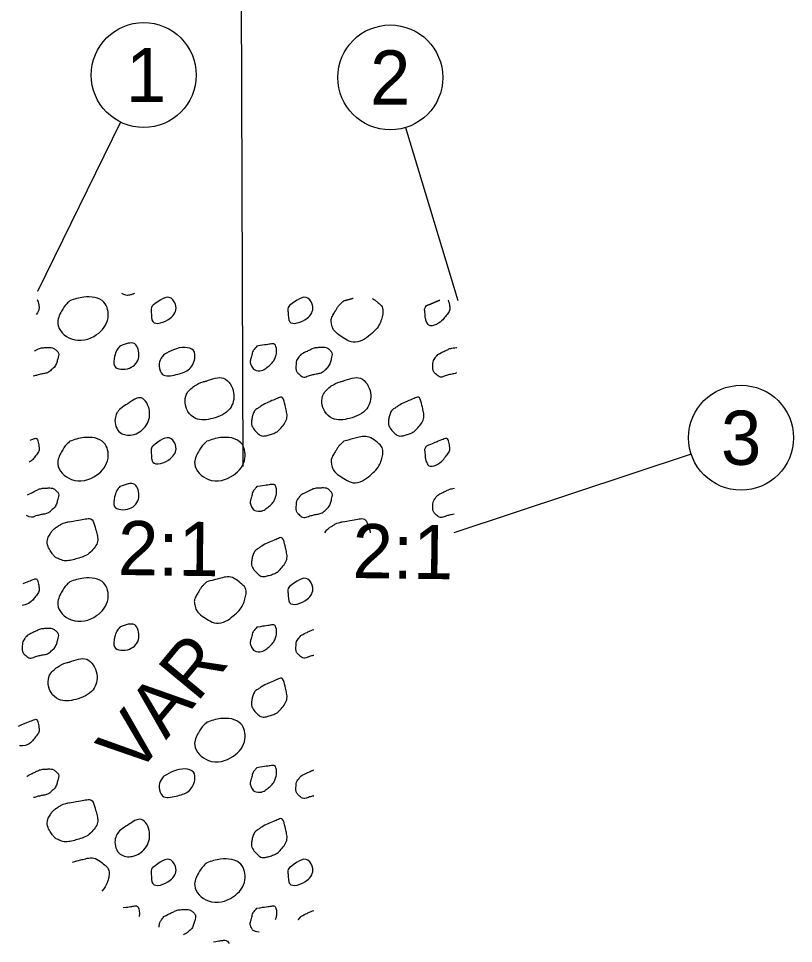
# Model space of a CAD drawing. Extents: x -1270 to 3371, y -118 to 220.
# Drawn here: x 98.85 to 118.87, y 155.01 to 178.92 of the extents above; entities that cross this region are included whole.
import ezdxf

# ---------------------------------------------------------------- set-up
doc = ezdxf.new("R2010")
doc.units = 0
for name, color, linetype in [('GE_P_Alignment', 7, 'Continuous'), ('GE_P_Alignment_100_Bearings', 7, 'Continuous'), ('TX_P_1', 7, 'Continuous')]:
    doc.layers.add(name, color=color, linetype=linetype)

msp = doc.modelspace()

# ---------------------------------------------------------------- linework, layer by layer
at = {"layer": 'GE_P_Alignment'}
for p, q in [((104.602, 180.507), (104.65, 167.338)), ((101.489, 176.239), (99.34, 171.86)), ((108.848, 176.097), (110.202, 171.63)), ((116.229, 167.658), (110.094, 165.63))]:
    msp.add_line(p, q, dxfattribs=at)
at = {"layer": 'GE_P_Alignment_100_Bearings'}
for points, degree in [([(99.33, 171.651), (99.36, 171.6), (99.377, 171.517), (99.382, 171.471), (99.388, 171.405), (99.357, 171.337), (99.311, 171.27)], 3), ([(101.848, 171.807), (101.829, 171.799), (101.809, 171.793), (101.789, 171.787), (101.706, 171.762), (101.604, 171.755), (101.517, 171.814)], 3), ([(107.99, 171.677), (108.036, 171.653), (108.082, 171.623), (108.128, 171.584), (108.263, 171.472), (108.272, 171.306), (108.236, 171.182), (108.191, 171.025), (108.092, 170.877), (107.94, 170.747), (107.75, 170.585), (107.486, 170.521), (107.292, 170.636), (107.134, 170.729), (106.968, 170.869), (106.938, 171.034), (106.919, 171.137), (106.972, 171.257), (107.033, 171.353), (107.076, 171.421), (107.114, 171.49), (107.171, 171.545), (107.198, 171.571), (107.225, 171.597), (107.252, 171.623)], 3), ([(107.252, 171.623), (107.333, 171.644), (107.415, 171.666), (107.496, 171.687)], 2), ([(109.946, 171.635), (109.971, 171.584), (109.985, 171.512), (109.989, 171.471), (109.999, 171.371), (109.922, 171.267), (109.84, 171.169), (109.729, 171.034), (109.448, 170.937), (109.39, 171.084), (109.359, 171.163), (109.354, 171.243), (109.351, 171.324), (109.349, 171.365), (109.334, 171.409), (109.355, 171.445), (109.366, 171.464), (109.377, 171.48), (109.388, 171.497)], 3), ([(109.388, 171.497), (109.504, 171.544), (109.62, 171.593), (109.736, 171.64)], 2), ([(99.265, 170.329), (99.284, 170.339), (99.303, 170.348), (99.323, 170.358), (99.414, 170.404), (99.524, 170.413), (99.623, 170.416), (99.697, 170.418), (99.768, 170.4), (99.834, 170.335), (99.895, 170.275), (99.886, 170.195), (99.868, 170.131), (99.839, 170.026), (99.8, 169.92), (99.698, 169.835), (99.598, 169.752), (99.492, 169.74), (99.384, 169.715), (99.336, 169.703), (99.284, 169.685), (99.233, 169.675)], 3), ([(105.007, 170.45), (105.134, 170.468), (105.261, 170.488), (105.388, 170.506), (105.502, 170.521), (105.528, 170.276), (105.493, 170.177), (105.453, 170.069), (105.354, 169.961), (105.253, 169.883), (105.148, 169.803), (104.927, 169.816), (104.866, 169.94), (104.828, 170.017), (104.847, 170.108), (104.868, 170.186), (104.884, 170.241), (104.891, 170.304), (104.927, 170.349), (104.953, 170.383), (104.98, 170.416), (105.007, 170.45)], 3), ([(106.144, 170.233), (106.227, 170.275), (106.311, 170.316), (106.394, 170.358), (106.486, 170.404), (106.595, 170.413), (106.695, 170.416), (106.769, 170.418), (106.84, 170.4), (106.906, 170.335), (106.967, 170.275), (106.958, 170.195), (106.94, 170.131), (106.911, 170.026), (106.871, 169.92), (106.769, 169.835), (106.669, 169.752), (106.563, 169.74), (106.456, 169.715), (106.343, 169.689), (106.214, 169.622), (106.104, 169.721), (106.032, 169.786), (106.016, 169.862), (106.018, 169.936), (106.02, 170.003), (106.028, 170.081), (106.07, 170.136), (106.095, 170.169), (106.119, 170.201), (106.144, 170.233)], 3), ([(110.165, 169.757), (110.108, 169.738), (110.05, 169.728), (109.992, 169.715), (109.879, 169.689), (109.75, 169.622), (109.64, 169.721), (109.567, 169.786), (109.552, 169.862), (109.554, 169.936), (109.556, 170.003), (109.564, 170.081), (109.606, 170.136), (109.631, 170.169), (109.655, 170.201), (109.68, 170.233)], 3), ([(109.68, 170.233), (109.763, 170.275), (109.847, 170.316), (109.93, 170.358), (110.005, 170.396), (110.093, 170.408), (110.177, 170.413)], 3), ([(105.211, 168.961), (105.328, 169.012), (105.445, 169.062), (105.563, 169.112), (105.684, 169.164), (105.743, 168.898), (105.77, 168.774), (105.798, 168.643), (105.764, 168.496), (105.658, 168.369), (105.559, 168.249), (105.445, 168.193), (105.325, 168.156), (105.229, 168.127), (105.108, 168.123), (105.014, 168.216), (104.9, 168.328), (104.858, 168.46), (104.881, 168.575), (104.899, 168.666), (104.942, 168.786), (105.027, 168.842), (105.088, 168.883), (105.15, 168.921), (105.211, 168.961)], 3), ([(108.747, 168.961), (108.864, 169.012), (108.981, 169.062), (109.098, 169.112), (109.22, 169.164), (109.279, 168.898), (109.306, 168.774), (109.334, 168.643), (109.3, 168.496), (109.194, 168.369), (109.095, 168.249), (108.981, 168.193), (108.861, 168.156), (108.765, 168.127), (108.644, 168.123), (108.55, 168.216), (108.436, 168.328), (108.394, 168.46), (108.417, 168.575), (108.435, 168.666), (108.477, 168.786), (108.563, 168.842), (108.624, 168.883), (108.685, 168.921), (108.747, 168.961)], 3), ([(99.151, 168.018), (99.186, 168.032), (99.221, 168.046), (99.256, 168.059), (99.334, 168.089), (99.375, 167.915), (99.382, 167.841), (99.391, 167.741), (99.315, 167.637), (99.233, 167.538), (99.205, 167.505), (99.166, 167.473), (99.123, 167.448)], 3), ([(107.252, 167.992), (107.37, 168.024), (107.489, 168.055), (107.608, 168.086), (107.781, 168.13), (107.955, 168.099), (108.128, 167.954), (108.263, 167.842), (108.272, 167.675), (108.236, 167.551), (108.191, 167.395), (108.092, 167.246), (107.94, 167.116), (107.75, 166.954), (107.486, 166.89), (107.292, 167.006), (107.134, 167.099), (106.968, 167.239), (106.938, 167.404), (106.919, 167.507), (106.972, 167.626), (107.033, 167.722), (107.076, 167.791), (107.114, 167.86), (107.171, 167.915), (107.198, 167.941), (107.225, 167.967), (107.252, 167.992)], 3), ([(109.388, 167.866), (109.547, 167.93), (109.705, 167.999), (109.863, 168.059), (109.941, 168.089), (109.982, 167.915), (109.989, 167.841), (109.999, 167.741), (109.922, 167.637), (109.84, 167.538), (109.729, 167.404), (109.448, 167.306), (109.39, 167.454), (109.359, 167.532), (109.354, 167.613), (109.351, 167.694), (109.349, 167.734), (109.334, 167.779), (109.355, 167.815), (109.366, 167.833), (109.377, 167.849), (109.388, 167.866)], 3), ([(105.007, 166.819), (105.134, 166.838), (105.261, 166.858), (105.388, 166.875), (105.502, 166.89), (105.528, 166.645), (105.493, 166.547), (105.453, 166.438), (105.354, 166.331), (105.253, 166.253), (105.148, 166.172), (104.927, 166.186), (104.866, 166.309), (104.828, 166.387), (104.847, 166.477), (104.868, 166.555), (104.884, 166.61), (104.891, 166.673), (104.927, 166.718), (104.953, 166.752), (104.98, 166.786), (105.007, 166.819)], 3), ([(99.082, 166.607), (99.162, 166.648), (99.242, 166.688), (99.323, 166.728), (99.414, 166.773), (99.524, 166.782), (99.623, 166.785), (99.697, 166.787), (99.768, 166.77), (99.834, 166.704), (99.895, 166.644), (99.886, 166.564), (99.868, 166.501), (99.839, 166.396), (99.8, 166.289), (99.698, 166.204), (99.598, 166.121), (99.492, 166.109), (99.384, 166.084), (99.279, 166.06), (99.161, 166), (99.056, 166.072)], 3), ([(106.144, 166.603), (106.227, 166.644), (106.311, 166.686), (106.394, 166.728), (106.486, 166.773), (106.595, 166.782), (106.695, 166.785), (106.769, 166.787), (106.84, 166.77), (106.906, 166.704), (106.967, 166.644), (106.958, 166.564), (106.94, 166.501), (106.911, 166.396), (106.871, 166.289), (106.769, 166.204), (106.669, 166.121), (106.563, 166.109), (106.456, 166.084), (106.343, 166.058), (106.214, 165.991), (106.104, 166.09), (106.032, 166.155), (106.016, 166.231), (106.018, 166.306), (106.02, 166.372), (106.028, 166.451), (106.07, 166.506), (106.095, 166.539), (106.119, 166.57), (106.144, 166.603)], 3), ([(110.101, 166.109), (110.065, 166.1), (110.028, 166.093), (109.992, 166.084), (109.879, 166.058), (109.75, 165.991), (109.64, 166.09), (109.567, 166.155), (109.552, 166.231), (109.554, 166.306), (109.556, 166.372), (109.564, 166.451), (109.606, 166.506), (109.631, 166.539), (109.655, 166.57), (109.68, 166.603)], 3), ([(109.68, 166.603), (109.763, 166.644), (109.847, 166.686), (109.93, 166.728), (109.986, 166.755), (110.049, 166.77), (110.112, 166.777)], 3), ([(100.159, 165.913), (100.311, 165.939), (100.462, 165.968), (100.613, 165.989), (100.765, 166.01), (100.835, 165.751), (100.873, 165.609), (100.907, 165.48), (100.885, 165.323), (100.776, 165.203), (100.643, 165.055), (100.495, 164.998), (100.33, 164.95), (100.189, 164.909), (100.031, 164.893), (99.89, 164.953), (99.805, 164.989), (99.743, 165.051), (99.691, 165.131), (99.604, 165.265), (99.579, 165.449), (99.654, 165.576), (99.704, 165.66), (99.772, 165.734), (99.859, 165.789), (99.933, 165.836), (100.003, 165.88), (100.085, 165.898), (100.113, 165.903), (100.14, 165.909), (100.168, 165.915)], 3), ([(106.762, 165.63), (106.807, 165.691), (106.863, 165.746), (106.931, 165.789), (107.005, 165.836), (107.075, 165.88), (107.157, 165.898), (107.184, 165.903), (107.212, 165.909), (107.239, 165.915)], 3), ([(107.231, 165.913), (107.382, 165.939), (107.534, 165.968), (107.685, 165.989), (107.829, 166.009), (107.9, 165.775), (107.939, 165.63)], 3), ([(105.211, 165.331), (105.328, 165.381), (105.445, 165.431), (105.563, 165.482), (105.684, 165.534), (105.743, 165.267), (105.77, 165.143), (105.798, 165.012), (105.764, 164.865), (105.658, 164.738), (105.559, 164.619), (105.445, 164.562), (105.325, 164.526), (105.229, 164.497), (105.108, 164.492), (105.014, 164.585), (104.9, 164.698), (104.858, 164.83), (104.881, 164.944), (104.899, 165.035), (104.942, 165.155), (105.027, 165.212), (105.088, 165.253), (105.15, 165.291), (105.211, 165.331)], 3), ([(98.97, 164.313), (99.065, 164.353), (99.16, 164.392), (99.256, 164.428), (99.334, 164.458), (99.375, 164.284), (99.382, 164.21), (99.391, 164.11), (99.315, 164.006), (99.233, 163.908), (99.167, 163.829), (99.044, 163.763), (98.942, 163.751)], 3), ([(103.716, 164.362), (103.834, 164.393), (103.953, 164.424), (104.072, 164.455), (104.245, 164.5), (104.419, 164.468), (104.593, 164.323), (104.727, 164.211), (104.736, 164.045), (104.7, 163.921), (104.655, 163.764), (104.556, 163.616), (104.404, 163.486), (104.214, 163.324), (103.95, 163.26), (103.756, 163.375), (103.598, 163.468), (103.432, 163.608), (103.402, 163.773), (103.383, 163.876), (103.436, 163.996), (103.497, 164.092), (103.54, 164.16), (103.578, 164.229), (103.635, 164.284), (103.662, 164.31), (103.689, 164.336), (103.716, 164.362)], 3), ([(105.007, 163.189), (105.134, 163.207), (105.261, 163.227), (105.388, 163.245), (105.502, 163.26), (105.528, 163.015), (105.493, 162.916), (105.453, 162.808), (105.354, 162.7), (105.253, 162.622), (105.148, 162.542), (104.927, 162.555), (104.866, 162.679), (104.828, 162.757), (104.847, 162.847), (104.868, 162.925), (104.884, 162.98), (104.891, 163.043), (104.927, 163.088), (104.953, 163.122), (104.98, 163.155), (105.007, 163.189)], 3), ([(99.073, 162.972), (99.156, 163.014), (99.239, 163.056), (99.323, 163.097), (99.414, 163.143), (99.524, 163.152), (99.623, 163.155), (99.697, 163.157), (99.768, 163.139), (99.834, 163.074), (99.895, 163.014), (99.886, 162.934), (99.868, 162.87), (99.839, 162.765), (99.8, 162.659), (99.698, 162.574), (99.598, 162.491), (99.492, 162.479), (99.384, 162.454), (99.272, 162.428), (99.143, 162.361), (99.033, 162.46), (98.96, 162.525), (98.945, 162.601), (98.947, 162.675), (98.949, 162.742), (98.957, 162.82), (98.998, 162.875), (99.023, 162.908), (99.048, 162.94), (99.073, 162.972)], 3), ([(106.144, 162.972), (106.227, 163.014), (106.311, 163.056), (106.394, 163.097), (106.422, 163.111), (106.452, 163.122), (106.483, 163.13)], 3), ([(106.483, 162.46), (106.474, 162.458), (106.465, 162.456), (106.456, 162.454), (106.343, 162.428), (106.214, 162.361), (106.104, 162.46), (106.032, 162.525), (106.016, 162.601), (106.018, 162.675), (106.02, 162.742), (106.028, 162.82), (106.07, 162.875), (106.095, 162.908), (106.119, 162.94), (106.144, 162.972)], 3), ([(105.211, 161.7), (105.328, 161.751), (105.445, 161.801), (105.563, 161.851), (105.684, 161.903), (105.743, 161.637), (105.77, 161.513), (105.798, 161.382), (105.764, 161.235), (105.658, 161.108), (105.559, 160.988), (105.445, 160.932), (105.325, 160.895), (105.229, 160.866), (105.108, 160.862), (105.014, 160.955), (104.9, 161.067), (104.858, 161.199), (104.881, 161.314), (104.899, 161.405), (104.942, 161.525), (105.027, 161.581), (105.088, 161.622), (105.15, 161.661), (105.211, 161.7)], 3), ([(98.851, 160.634), (98.986, 160.689), (99.121, 160.747), (99.256, 160.798), (99.334, 160.828), (99.375, 160.654), (99.382, 160.58), (99.391, 160.48), (99.315, 160.376), (99.233, 160.277), (99.153, 160.181), (98.986, 160.104), (98.877, 160.122)], 3), ([(99.073, 159.342), (99.156, 159.383), (99.239, 159.425), (99.323, 159.467), (99.414, 159.512), (99.524, 159.521), (99.623, 159.524), (99.697, 159.526), (99.768, 159.509), (99.834, 159.443), (99.895, 159.383), (99.886, 159.303), (99.868, 159.24), (99.839, 159.135), (99.8, 159.028), (99.698, 158.943), (99.598, 158.86), (99.492, 158.848), (99.384, 158.823), (99.336, 158.812), (99.285, 158.794), (99.234, 158.784)], 3), ([(105.007, 159.558), (105.134, 159.577), (105.261, 159.597), (105.388, 159.614), (105.502, 159.629), (105.528, 159.384), (105.493, 159.286), (105.453, 159.177), (105.354, 159.07), (105.253, 158.992), (105.148, 158.911), (104.927, 158.925), (104.866, 159.048), (104.828, 159.126), (104.847, 159.216), (104.868, 159.294), (104.884, 159.349), (104.891, 159.412), (104.927, 159.457), (104.953, 159.491), (104.98, 159.525), (105.007, 159.558)], 3), ([(106.144, 159.342), (106.227, 159.383), (106.311, 159.425), (106.394, 159.467), (106.422, 159.481), (106.452, 159.491), (106.483, 159.499)], 3), ([(99.067, 159.335), (99.069, 159.337), (99.071, 159.339), (99.073, 159.342)], 2), ([(106.483, 158.829), (106.474, 158.827), (106.465, 158.825), (106.456, 158.823), (106.343, 158.797), (106.214, 158.73), (106.104, 158.829), (106.032, 158.894), (106.016, 158.97), (106.018, 159.045), (106.02, 159.111), (106.028, 159.19), (106.07, 159.245), (106.095, 159.278), (106.119, 159.309), (106.144, 159.342)], 3), ([(100.159, 158.652), (100.311, 158.678), (100.462, 158.707), (100.613, 158.728), (100.765, 158.749), (100.835, 158.49), (100.873, 158.348), (100.907, 158.219), (100.885, 158.062), (100.776, 157.942), (100.643, 157.794), (100.495, 157.737), (100.33, 157.689), (100.189, 157.648), (100.031, 157.632), (99.89, 157.692), (99.805, 157.728), (99.743, 157.79), (99.691, 157.87), (99.604, 158.004), (99.579, 158.188), (99.654, 158.315), (99.704, 158.399), (99.772, 158.473), (99.859, 158.528), (99.933, 158.575), (100.003, 158.619), (100.085, 158.637), (100.113, 158.642), (100.14, 158.648), (100.168, 158.654)], 3), ([(105.211, 158.07), (105.328, 158.12), (105.445, 158.17), (105.563, 158.221), (105.684, 158.273), (105.743, 158.006), (105.77, 157.882), (105.798, 157.751), (105.764, 157.604), (105.658, 157.477), (105.559, 157.358), (105.445, 157.301), (105.325, 157.265), (105.229, 157.236), (105.108, 157.231), (105.014, 157.324), (104.9, 157.437), (104.858, 157.569), (104.881, 157.683), (104.899, 157.774), (104.942, 157.894), (105.027, 157.951), (105.088, 157.992), (105.15, 158.03), (105.211, 158.07)], 3), ([(100.242, 157.117), (100.34, 157.143), (100.438, 157.169), (100.536, 157.194), (100.709, 157.239), (100.884, 157.207), (101.057, 157.062), (101.191, 156.95), (101.2, 156.784), (101.164, 156.66), (101.135, 156.557), (101.082, 156.458), (101.006, 156.365)], 3), ([(101.558, 155.941), (101.656, 155.955), (101.755, 155.97), (101.853, 155.984), (101.947, 155.996), (101.981, 155.828), (101.969, 155.715)], 3), ([(102.608, 155.711), (102.692, 155.753), (102.775, 155.795), (102.858, 155.836), (102.95, 155.882), (103.059, 155.891), (103.159, 155.894), (103.233, 155.896), (103.304, 155.879), (103.37, 155.813), (103.431, 155.753), (103.422, 155.673), (103.404, 155.609), (103.375, 155.504), (103.336, 155.398), (103.233, 155.313), (103.193, 155.279), (103.152, 155.257), (103.109, 155.241)], 3), ([(105.067, 155.311), (104.982, 155.315), (104.9, 155.35), (104.866, 155.418), (104.828, 155.496), (104.847, 155.586), (104.868, 155.664), (104.884, 155.719), (104.891, 155.782), (104.927, 155.827), (104.953, 155.861), (104.98, 155.894), (105.007, 155.928)], 3), ([(105.007, 155.928), (105.134, 155.946), (105.261, 155.966), (105.388, 155.984), (105.502, 155.999), (105.528, 155.754), (105.493, 155.655), (105.489, 155.647), (105.486, 155.638), (105.482, 155.63)], 3), ([(106.144, 155.711), (106.227, 155.753), (106.311, 155.795), (106.394, 155.836), (106.422, 155.85), (106.452, 155.861), (106.483, 155.869)], 3), ([(102.483, 155.435), (102.486, 155.496), (102.497, 155.565), (102.534, 155.614), (102.559, 155.647), (102.584, 155.679), (102.608, 155.711)], 3), ([(106.082, 155.63), (106.102, 155.657), (106.123, 155.684), (106.144, 155.711)], 2), ([(103.886, 155.055), (103.974, 155.071), (104.062, 155.086), (104.149, 155.098), (104.209, 155.106), (104.257, 155.07), (104.294, 155.015)], 3)]:
    msp.add_open_spline(points, degree=degree, dxfattribs=at)
for points in [[(100.18, 171.623), (100.536, 171.716), (101.057, 171.584), (101.164, 171.182), (100.868, 170.747), (100.22, 170.636), (99.866, 171.034), (99.961, 171.353), (100.099, 171.545), (100.18, 171.623)], [(102.317, 171.497), (102.792, 171.689), (102.918, 171.471), (102.768, 171.169), (102.318, 171.084), (102.279, 171.324), (102.283, 171.445), (102.317, 171.497)], [(105.853, 171.497), (106.328, 171.689), (106.453, 171.471), (106.304, 171.169), (105.854, 171.084), (105.815, 171.324), (105.819, 171.445), (105.853, 171.497)], [(101.471, 170.45), (101.853, 170.506), (101.957, 170.177), (101.717, 169.883), (101.33, 169.94), (101.333, 170.186), (101.391, 170.349), (101.471, 170.45)], [(102.608, 170.233), (102.858, 170.358), (103.159, 170.416), (103.37, 170.335), (103.404, 170.131), (103.233, 169.835), (102.92, 169.715), (102.568, 169.721), (102.483, 169.936), (102.534, 170.136), (102.608, 170.233)], [(103.695, 169.544), (104.149, 169.62), (104.408, 169.24), (104.312, 168.833), (103.866, 168.581), (103.426, 168.583), (103.227, 168.761), (103.19, 169.206), (103.395, 169.42), (103.621, 169.528), (103.703, 169.546)], [(107.231, 169.544), (107.685, 169.62), (107.944, 169.24), (107.848, 168.833), (107.402, 168.581), (106.962, 168.583), (106.763, 168.761), (106.726, 169.206), (106.931, 169.42), (107.157, 169.528), (107.239, 169.546)], [(101.675, 168.961), (102.027, 169.112), (102.234, 168.774), (102.123, 168.369), (101.789, 168.156), (101.478, 168.216), (101.345, 168.575), (101.491, 168.842), (101.675, 168.961)], [(100.18, 167.992), (100.536, 168.086), (101.057, 167.954), (101.164, 167.551), (100.868, 167.116), (100.22, 167.006), (99.866, 167.404), (99.961, 167.722), (100.099, 167.915), (100.18, 167.992)], [(102.317, 167.866), (102.792, 168.059), (102.918, 167.841), (102.768, 167.538), (102.318, 167.454), (102.279, 167.694), (102.283, 167.815), (102.317, 167.866)], [(103.716, 167.992), (104.072, 168.086), (104.593, 167.954), (104.7, 167.551), (104.404, 167.116), (103.756, 167.006), (103.402, 167.404), (103.497, 167.722), (103.635, 167.915), (103.716, 167.992)], [(101.471, 166.819), (101.853, 166.875), (101.957, 166.547), (101.717, 166.253), (101.33, 166.309), (101.333, 166.555), (101.391, 166.718), (101.471, 166.819)], [(100.18, 164.362), (100.536, 164.455), (101.057, 164.323), (101.164, 163.921), (100.868, 163.486), (100.22, 163.375), (99.866, 163.773), (99.961, 164.092), (100.099, 164.284), (100.18, 164.362)], [(105.853, 164.236), (106.328, 164.428), (106.453, 164.21), (106.304, 163.908), (105.854, 163.823), (105.815, 164.063), (105.819, 164.184), (105.853, 164.236)], [(101.471, 163.189), (101.853, 163.245), (101.957, 162.916), (101.717, 162.622), (101.33, 162.679), (101.333, 162.925), (101.391, 163.088), (101.471, 163.189)], [(100.159, 162.283), (100.613, 162.359), (100.873, 161.979), (100.776, 161.572), (100.33, 161.32), (99.89, 161.322), (99.691, 161.5), (99.654, 161.945), (99.859, 162.159), (100.085, 162.267), (100.168, 162.285)], [(103.716, 160.731), (104.072, 160.825), (104.593, 160.693), (104.7, 160.29), (104.404, 159.855), (103.756, 159.745), (103.402, 160.143), (103.497, 160.461), (103.635, 160.654), (103.716, 160.731)], [(102.608, 159.342), (102.858, 159.467), (103.159, 159.524), (103.37, 159.443), (103.404, 159.24), (103.233, 158.943), (102.92, 158.823), (102.568, 158.829), (102.483, 159.045), (102.534, 159.245), (102.608, 159.342)], [(101.675, 158.07), (102.027, 158.221), (102.234, 157.882), (102.123, 157.477), (101.789, 157.265), (101.478, 157.324), (101.345, 157.683), (101.491, 157.951), (101.675, 158.07)], [(102.317, 156.975), (102.792, 157.167), (102.918, 156.949), (102.768, 156.647), (102.318, 156.562), (102.279, 156.802), (102.283, 156.923), (102.317, 156.975)], [(103.716, 157.101), (104.072, 157.194), (104.593, 157.062), (104.7, 156.66), (104.404, 156.225), (103.756, 156.114), (103.402, 156.512), (103.497, 156.831), (103.635, 157.023), (103.716, 157.101)], [(105.853, 156.975), (106.328, 157.167), (106.453, 156.949), (106.304, 156.647), (105.854, 156.562), (105.815, 156.802), (105.819, 156.923), (105.853, 156.975)]]:
    msp.add_spline(points, degree=3, dxfattribs=at)
at = {"layer": 'TX_P_1'}
for centre in [(102.085, 177.455), (108.455, 177.393), (117.515, 168.083)]:
    msp.add_circle(centre, 1.355, dxfattribs=at)

# ---------------------------------------------------------------- texts
for s, p in [('1', (101.627, 176.755)), ('2', (107.933, 176.693)), ('3', (116.997, 167.383))]:
    msp.add_text(s, height=1.4, dxfattribs=at).set_placement(p)
for s, rotation, p in [('2:1', 359.25, (101.413, 164.538)), ('2:1', 359.25, (107.472, 164.459)), ('VAR', 50.3125, (101.863, 159.3))]:
    msp.add_text(s, height=1.4, rotation=rotation, dxfattribs=at).set_placement(p)

doc.saveas('drawing.dxf')
